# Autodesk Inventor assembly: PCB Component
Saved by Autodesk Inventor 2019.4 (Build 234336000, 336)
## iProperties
Created: 2020-03
Part Number: PCB Component
Document SubType Name: Assembly
Designer: Administrator
Title: PCB Component
Author: Administrator
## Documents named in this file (12)
- c:\worker\convert-fusion-r02\tmp\job-1\1612\output\files\65dcbb1a-1ec9-4cec-af47-cc4d06111fe3\PCB Component.iam
- c:\worker\convert-fusion-r02\tmp\job-1\1612\output\files\65dcbb1a-1ec9-4cec-af47-cc4d06111fe3\Board.ipt
- c:\worker\convert-fusion-r02\tmp\job-1\1612\output\files\65dcbb1a-1ec9-4cec-af47-cc4d06111fe3\DIL16.ipt
- c:\worker\convert-fusion-r02\tmp\job-1\1612\output\files\65dcbb1a-1ec9-4cec-af47-cc4d06111fe3\MODULE_ESP32-DEVKITC.ipt
- c:\worker\convert-fusion-r02\tmp\job-1\1612\output\files\65dcbb1a-1ec9-4cec-af47-cc4d06111fe3\1X04.ipt
- c:\worker\convert-fusion-r02\tmp\job-1\1612\output\files\65dcbb1a-1ec9-4cec-af47-cc4d06111fe3\1X19.ipt
- c:\worker\convert-fusion-r02\tmp\job-1\1612\output\files\65dcbb1a-1ec9-4cec-af47-cc4d06111fe3\1X06.ipt
- c:\worker\convert-fusion-r02\tmp\job-1\1612\output\files\65dcbb1a-1ec9-4cec-af47-cc4d06111fe3\1X02.ipt
- c:\worker\convert-fusion-r02\tmp\job-1\1612\output\files\65dcbb1a-1ec9-4cec-af47-cc4d06111fe3\1X03.ipt
- c:\worker\convert-fusion-r02\tmp\job-1\1612\output\files\65dcbb1a-1ec9-4cec-af47-cc4d06111fe3\R0805.ipt
- c:\worker\convert-fusion-r02\tmp\job-1\1612\output\files\65dcbb1a-1ec9-4cec-af47-cc4d06111fe3\DSN-1504.ipt
- c:\worker\convert-fusion-r02\tmp\job-1\1612\output\files\65dcbb1a-1ec9-4cec-af47-cc4d06111fe3\DO27-15.ipt
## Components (17 placed, 17 different names)
1. Board:1
2. DIL16:MOT1-2_H
3. DIL16:MOT3_H
4. MODULE_ESP32-DEVKITC:U1
5. 1X04:MPU9250
6. 1X04:VL53L0X
7. 1X19:JP6
8. 1X19:JP7
9. 1X06:MOT3_HD
10. 1X06:MOT2_HD
11. 1X06:MOT1_HD
12. 1X02:JP1
13. 1X03:JP2
14. R0805:R1
15. R0805:R2
16. DSN-1504:U$1
17. DO27-15:D2
